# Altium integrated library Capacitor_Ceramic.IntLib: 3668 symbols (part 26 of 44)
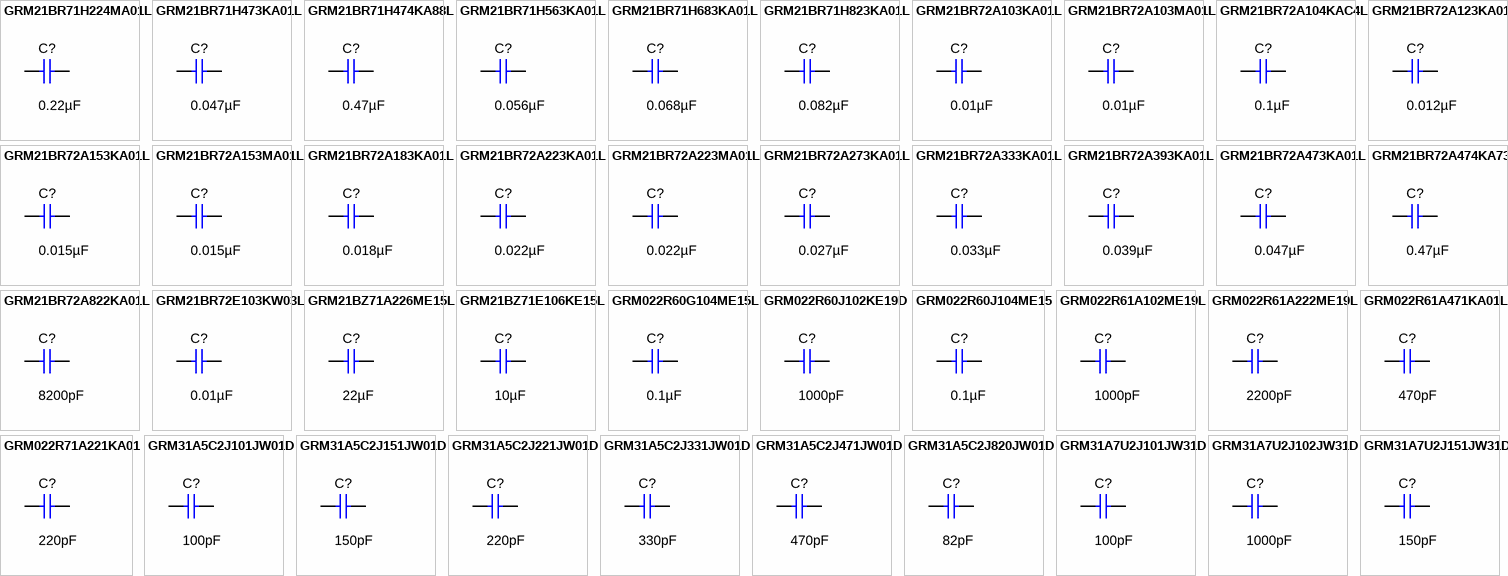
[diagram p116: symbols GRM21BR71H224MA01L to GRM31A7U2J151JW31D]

## GRM022R61A222ME19L
designator C?  ValueDisplayed: 2200pF  (hidden comment: GRM022R61A222ME19L)
CAP, CERM, 2200 pF, 10 V,+/- 20%, X5R, 01005; Manufacturer: MuRata; Polarized: N; CompType: Capacitor; Value: 2200pF; U/M: EA; Cap_F: 0.0000000022; Tolerance_%: 20; VDC_V: 10; Value2: 10V; TaMin_C: -55; TaMax_C: 85; Cap_Case: 01005; SizeArea_mm2: 0.08; SizeAreaWB_mm2: 1.68; SizeX_mm: 0.4; SizeY_mm: 0.2; AEC Category: Q200
signal-integrity model Cap
simulation model Cap
footprint 01005
pins: 1, 2

## GRM022R61A471KA01L
designator C?  ValueDisplayed: 470pF  (hidden comment: GRM022R61A471KA01L)
CAP, CERM, 470 pF, 10 V,+/- 10%, X5R, 01005; Manufacturer: MuRata; Polarized: N; CompType: Capacitor; Value: 470pF; U/M: EA; Cap_F: 0.00000000047; Tolerance_%: 10; Value2: 10V; TaMin_C: -55; TaMax_C: 85; Cap_Case: 01005; SizeArea_mm2: 0.08; SizeAreaWB_mm2: 1.68; SizeX_mm: 0.4; SizeY_mm: 0.2; AEC Category: Q200
signal-integrity model Cap
simulation model Cap
footprint 01005
pins: 1, 2

## GRM022R71A221KA01
designator C?  ValueDisplayed: 220pF  (hidden comment: GRM022R71A221KA01)
CAP, CERM, 220 pF, 10 V,+/- 10%, X7R, 01005; Manufacturer: MuRata; Polarized: N; CompType: Capacitor; Value: 220pF; U/M: EA; Cap_F: 0.00000000022; Tolerance_%: 10; Value2: 10V; TaMin_C: -55; TaMax_C: 125; Cap_Case: 01005; SizeArea_mm2: 0.08; SizeAreaWB_mm2: 1.68; SizeX_mm: 0.4; SizeY_mm: 0.2; AEC Category: Q200
signal-integrity model Cap
simulation model Cap
footprint 01005
pins: 1, 2

## GRM31A5C2J101JW01D
designator C?  ValueDisplayed: 100pF  (hidden comment: GRM31A5C2J101JW01D)
CAP, CERM, 100 pF, 630 V,+/- 5%, C0G/NP0, 1206; Manufacturer: MuRata; Polarized: N; CompType: Capacitor; Value: 100pF; U/M: EA; Cap_F: 0.0000000001; Tolerance_%: 5; VDC_V: 630; Value2: 630V; TaMin_C: -55; TaMax_C: 125; Cap_Case: 1206; SizeArea_mm2: 5.12; SizeAreaWB_mm2: 10.92; SizeX_mm: 3.2; SizeY_mm: 1.6; SizeZ_mm: 1.35; AEC Category: Q200; Green_Lifecycle: Not Set; Green_REACh: Incomplete
signal-integrity model Cap
simulation model Cap
footprint 1206
footprint 1206M
footprint 1206L
pins: 1, 2

## GRM31A5C2J151JW01D
designator C?  ValueDisplayed: 150pF  (hidden comment: GRM31A5C2J151JW01D)
CAP, CERM, 150 pF, 630 V,+/- 5%, C0G/NP0, 1206; Manufacturer: MuRata; Polarized: N; CompType: Capacitor; Value: 150pF; U/M: EA; Cap_F: 0.00000000015; Tolerance_%: 5; VDC_V: 630; Value2: 630V; TaMin_C: -55; TaMax_C: 125; Cap_Case: 1206; SizeArea_mm2: 5.12; SizeAreaWB_mm2: 10.92; SizeX_mm: 3.2; SizeY_mm: 1.6; SizeZ_mm: 1.35; AEC Category: Q200
signal-integrity model Cap
simulation model Cap
footprint 1206
footprint 1206M
footprint 1206L
pins: 1, 2

## GRM31A5C2J221JW01D
designator C?  ValueDisplayed: 220pF  (hidden comment: GRM31A5C2J221JW01D)
CAP, CERM, 220 pF, 630 V,+/- 5%, C0G/NP0, 1206; Manufacturer: MuRata; Polarized: N; CompType: Capacitor; Value: 220pF; U/M: EA; Cap_F: 0.00000000022; Tolerance_%: 5; VDC_V: 630; Value2: 630V; TaMin_C: -55; TaMax_C: 125; Cap_Case: 1206; SizeArea_mm2: 5.12; SizeAreaWB_mm2: 10.92; SizeX_mm: 3.2; SizeY_mm: 1.6; SizeZ_mm: 1.35; AEC Category: Q200
signal-integrity model Cap
simulation model Cap
footprint 1206
footprint 1206M
footprint 1206L
pins: 1, 2

## GRM31A5C2J331JW01D
designator C?  ValueDisplayed: 330pF  (hidden comment: GRM31A5C2J331JW01D)
CAP, CERM, 330 pF, 630 V,+/- 5%, C0G/NP0, 1206; Manufacturer: MuRata; Polarized: N; CompType: Capacitor; Value: 330pF; U/M: EA; Cap_F: 0.00000000033; Tolerance_%: 5; VDC_V: 630; Value2: 630V; TaMin_C: -55; TaMax_C: 125; Cap_Case: 1206; SizeArea_mm2: 5.12; SizeAreaWB_mm2: 10.92; SizeX_mm: 3.2; SizeY_mm: 1.6; SizeZ_mm: 1.35; AEC Category: Q200
signal-integrity model Cap
simulation model Cap
footprint 1206
footprint 1206M
footprint 1206L
pins: 1, 2

## GRM31A5C2J471JW01D
designator C?  ValueDisplayed: 470pF  (hidden comment: GRM31A5C2J471JW01D)
CAP, CERM, 470 pF, 630 V,+/- 5%, C0G/NP0, 1206; Manufacturer: MuRata; Polarized: N; CompType: Capacitor; Value: 470pF; U/M: EA; Cap_F: 0.00000000047; Tolerance_%: 5; VDC_V: 630; Value2: 630V; TaMin_C: -55; TaMax_C: 125; Cap_Case: 1206; SizeArea_mm2: 5.12; SizeAreaWB_mm2: 10.92; SizeX_mm: 3.2; SizeY_mm: 1.6; SizeZ_mm: 1.35; AEC Category: Q200; Green_Lifecycle: Not Set; Green_REACh: Incomplete
signal-integrity model Cap
simulation model Cap
footprint 1206
footprint 1206M
footprint 1206L
pins: 1, 2

## GRM31A5C2J820JW01D
designator C?  ValueDisplayed: 82pF  (hidden comment: GRM31A5C2J820JW01D)
CAP, CERM, 82 pF, 630 V,+/- 5%, C0G/NP0, 1206; Manufacturer: MuRata; Polarized: N; CompType: Capacitor; Value: 82pF; U/M: EA; Cap_F: 0.000000000082; Tolerance_%: 5; VDC_V: 630; Value2: 630V; TaMin_C: -55; TaMax_C: 125; Cap_Case: 1206; SizeArea_mm2: 5.12; SizeAreaWB_mm2: 10.92; SizeX_mm: 3.2; SizeY_mm: 1.6; SizeZ_mm: 1.35; AEC Category: Q200
signal-integrity model Cap
simulation model Cap
footprint 1206
footprint 1206M
footprint 1206L
pins: 1, 2

## GRM31A7U2J101JW31D
designator C?  ValueDisplayed: 100pF  (hidden comment: GRM31A7U2J101JW31D)
CAP, CERM, 100 pF, 630 V,+/- 5%, U2J, 1206; Manufacturer: MuRata; Polarized: N; CompType: Capacitor; Value: 100pF; U/M: EA; Cap_F: 0.0000000001; Tolerance_%: 5; VDC_V: 630; Value2: 630V; TaMin_C: -55; TaMax_C: 125; Cap_Case: 1206; SizeArea_mm2: 5.12; SizeAreaWB_mm2: 10.92; SizeX_mm: 3.2; SizeY_mm: 1.6; SizeZ_mm: 1.35; AEC Category: Q200
signal-integrity model Cap
simulation model Cap
footprint 1206
footprint 1206M
footprint 1206L
pins: 1, 2

## GRM31A7U2J102JW31D
designator C?  ValueDisplayed: 1000pF  (hidden comment: GRM31A7U2J102JW31D)
CAP, CERM, 1000 pF, 630 V,+/- 5%, U2J, 1206; Manufacturer: MuRata; Polarized: N; CompType: Capacitor; Value: 1000pF; U/M: EA; Cap_F: 0.000000001; Tolerance_%: 5; VDC_V: 630; Value2: 630V; TaMin_C: -55; TaMax_C: 125; Cap_Case: 1206; SizeArea_mm2: 5.12; SizeAreaWB_mm2: 10.92; SizeX_mm: 3.2; SizeY_mm: 1.6; SizeZ_mm: 1.35; AEC Category: Q200
signal-integrity model Cap
simulation model Cap
footprint 1206
footprint 1206M
footprint 1206L
pins: 1, 2

## GRM31A7U2J151JW31D
designator C?  ValueDisplayed: 150pF  (hidden comment: GRM31A7U2J151JW31D)
CAP, CERM, 150 pF, 630 V,+/- 5%, U2J, 1206; Manufacturer: MuRata; Polarized: N; CompType: Capacitor; Value: 150pF; U/M: EA; Cap_F: 0.00000000015; Tolerance_%: 5; VDC_V: 630; Value2: 630V; TaMin_C: -55; TaMax_C: 125; Cap_Case: 1206; SizeArea_mm2: 5.12; SizeAreaWB_mm2: 10.92; SizeX_mm: 3.2; SizeY_mm: 1.6; SizeZ_mm: 1.35; AEC Category: Q200
signal-integrity model Cap
simulation model Cap
footprint 1206
footprint 1206M
footprint 1206L
pins: 1, 2

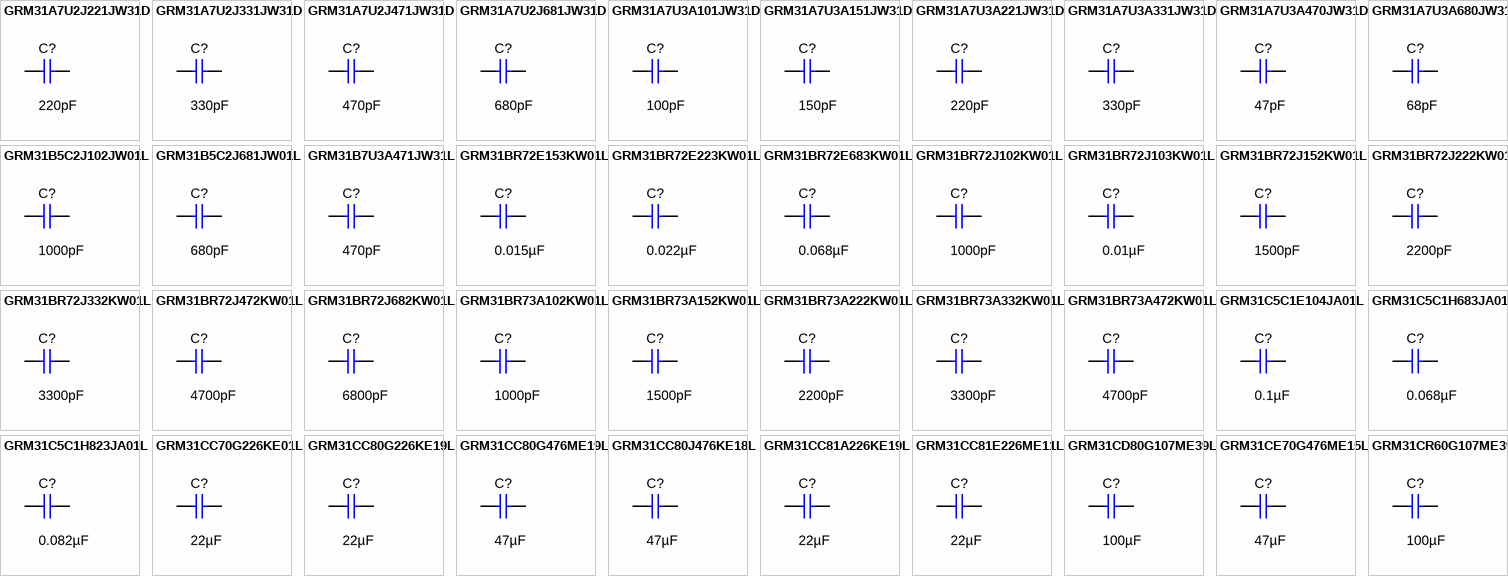
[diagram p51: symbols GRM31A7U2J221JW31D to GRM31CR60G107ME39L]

## GRM31A7U2J221JW31D
designator C?  ValueDisplayed: 220pF  (hidden comment: GRM31A7U2J221JW31D)
CAP, CERM, 220 pF, 630 V,+/- 5%, U2J, 1206; Manufacturer: MuRata; Polarized: N; CompType: Capacitor; Value: 220pF; U/M: EA; Cap_F: 0.00000000022; Tolerance_%: 5; VDC_V: 630; Value2: 630V; TaMin_C: -55; TaMax_C: 125; Cap_Case: 1206; SizeArea_mm2: 5.12; SizeAreaWB_mm2: 10.92; SizeX_mm: 3.2; SizeY_mm: 1.6; SizeZ_mm: 1.35; AEC Category: Q200
signal-integrity model Cap
simulation model Cap
footprint 1206
footprint 1206M
footprint 1206L
pins: 1, 2

## GRM31A7U2J331JW31D
designator C?  ValueDisplayed: 330pF  (hidden comment: GRM31A7U2J331JW31D)
CAP, CERM, 330 pF, 630 V,+/- 5%, U2J, 1206; Manufacturer: MuRata; Polarized: N; CompType: Capacitor; Value: 330pF; U/M: EA; Cap_F: 0.00000000033; Tolerance_%: 5; VDC_V: 630; Value2: 630V; TaMin_C: -55; TaMax_C: 125; Cap_Case: 1206; SizeArea_mm2: 5.12; SizeAreaWB_mm2: 10.92; SizeX_mm: 3.2; SizeY_mm: 1.6; SizeZ_mm: 1.35; AEC Category: Q200
signal-integrity model Cap
simulation model Cap
footprint 1206
footprint 1206M
footprint 1206L
pins: 1, 2

## GRM31A7U2J471JW31D
designator C?  ValueDisplayed: 470pF  (hidden comment: GRM31A7U2J471JW31D)
CAP, CERM, 470 pF, 630 V,+/- 5%, U2J, 1206; Manufacturer: MuRata; Polarized: N; CompType: Capacitor; Value: 470pF; U/M: EA; Cap_F: 0.00000000047; Tolerance_%: 5; VDC_V: 630; Value2: 630V; TaMin_C: -55; TaMax_C: 125; Cap_Case: 1206; SizeArea_mm2: 5.12; SizeAreaWB_mm2: 10.92; SizeX_mm: 3.2; SizeY_mm: 1.6; SizeZ_mm: 1.35; AEC Category: Q200; Green_Lifecycle: Not Set; Green_REACh: Incomplete
signal-integrity model Cap
simulation model Cap
footprint 1206
footprint 1206M
footprint 1206L
pins: 1, 2

## GRM31A7U2J681JW31D
designator C?  ValueDisplayed: 680pF  (hidden comment: GRM31A7U2J681JW31D)
CAP, CERM, 680 pF, 630 V,+/- 5%, U2J, 1206; Manufacturer: MuRata; Polarized: N; CompType: Capacitor; Value: 680pF; U/M: EA; Cap_F: 0.00000000068; Tolerance_%: 5; VDC_V: 630; Value2: 630V; TaMin_C: -55; TaMax_C: 125; Cap_Case: 1206; SizeArea_mm2: 5.12; SizeAreaWB_mm2: 10.92; SizeX_mm: 3.2; SizeY_mm: 1.6; SizeZ_mm: 1.35; AEC Category: Q200
signal-integrity model Cap
simulation model Cap
footprint 1206
footprint 1206M
footprint 1206L
pins: 1, 2

## GRM31A7U3A101JW31D
designator C?  ValueDisplayed: 100pF  (hidden comment: GRM31A7U3A101JW31D)
CAP, CERM, 100 pF, 1000 V,+/- 5%, U2J, 1206; Manufacturer: MuRata; Polarized: N; CompType: Capacitor; Value: 100pF; U/M: EA; Cap_F: 0.0000000001; Tolerance_%: 5; VDC_V: 1000; Value2: 1000V; TaMin_C: -55; TaMax_C: 125; Cap_Case: 1206; SizeArea_mm2: 5.12; SizeAreaWB_mm2: 10.92; SizeX_mm: 3.2; SizeY_mm: 1.6; SizeZ_mm: 1.35; AEC Category: Q200
signal-integrity model Cap
simulation model Cap
footprint 1206
footprint 1206M
footprint 1206L
pins: 1, 2

## GRM31A7U3A151JW31D
designator C?  ValueDisplayed: 150pF  (hidden comment: GRM31A7U3A151JW31D)
CAP, CERM, 150 pF, 1000 V,+/- 5%, U2J, 1206; Manufacturer: MuRata; Polarized: N; CompType: Capacitor; Value: 150pF; U/M: EA; Cap_F: 0.00000000015; Tolerance_%: 5; VDC_V: 1000; Value2: 1000V; TaMin_C: -55; TaMax_C: 125; Cap_Case: 1206; SizeArea_mm2: 5.12; SizeAreaWB_mm2: 10.92; SizeX_mm: 3.2; SizeY_mm: 1.6; SizeZ_mm: 1.35; AEC Category: Q200
signal-integrity model Cap
simulation model Cap
footprint 1206
footprint 1206M
footprint 1206L
pins: 1, 2

## GRM31A7U3A221JW31D
designator C?  ValueDisplayed: 220pF  (hidden comment: GRM31A7U3A221JW31D)
CAP, CERM, 220 pF, 1000 V,+/- 5%, U2J, 1206; Manufacturer: MuRata; Polarized: N; CompType: Capacitor; Value: 220pF; U/M: EA; Cap_F: 0.00000000022; Tolerance_%: 5; VDC_V: 1000; Value2: 1000V; TaMin_C: -55; TaMax_C: 125; Cap_Case: 1206; SizeArea_mm2: 5.12; SizeAreaWB_mm2: 10.92; SizeX_mm: 3.2; SizeY_mm: 1.6; SizeZ_mm: 1.35; AEC Category: Q200
signal-integrity model Cap
simulation model Cap
footprint 1206
footprint 1206M
footprint 1206L
pins: 1, 2

## GRM31A7U3A331JW31D
designator C?  ValueDisplayed: 330pF  (hidden comment: GRM31A7U3A331JW31D)
CAP, CERM, 330 pF, 1000 V,+/- 5%, U2J, 1206; Manufacturer: MuRata; Polarized: N; CompType: Capacitor; Value: 330pF; U/M: EA; Cap_F: 0.00000000033; Tolerance_%: 5; VDC_V: 1000; Value2: 1000V; TaMin_C: -55; TaMax_C: 125; Cap_Case: 1206; SizeArea_mm2: 5.12; SizeAreaWB_mm2: 10.92; SizeX_mm: 3.2; SizeY_mm: 1.6; SizeZ_mm: 1.35; AEC Category: Q200
signal-integrity model Cap
simulation model Cap
footprint 1206
footprint 1206M
footprint 1206L
pins: 1, 2

## GRM31A7U3A470JW31D
designator C?  ValueDisplayed: 47pF  (hidden comment: GRM31A7U3A470JW31D)
CAP, CERM, 47 pF, 1000 V,+/- 5%, U2J, 1206; Manufacturer: MuRata; Polarized: N; CompType: Capacitor; Value: 47pF; U/M: EA; Cap_F: 0.000000000047; Tolerance_%: 5; VDC_V: 1000; Value2: 1000V; TaMin_C: -55; TaMax_C: 125; Cap_Case: 1206; SizeArea_mm2: 5.12; SizeAreaWB_mm2: 10.92; SizeX_mm: 3.2; SizeY_mm: 1.6; SizeZ_mm: 1.35; AEC Category: Q200
signal-integrity model Cap
simulation model Cap
footprint 1206
footprint 1206M
footprint 1206L
pins: 1, 2

## GRM31A7U3A680JW31D
designator C?  ValueDisplayed: 68pF  (hidden comment: GRM31A7U3A680JW31D)
CAP, CERM, 68 pF, 1000 V,+/- 5%, U2J, 1206; Manufacturer: MuRata; Polarized: N; CompType: Capacitor; Value: 68pF; U/M: EA; Cap_F: 0.000000000068; Tolerance_%: 5; VDC_V: 1000; Value2: 1000V; TaMin_C: -55; TaMax_C: 125; Cap_Case: 1206; SizeArea_mm2: 5.12; SizeAreaWB_mm2: 10.92; SizeX_mm: 3.2; SizeY_mm: 1.6; SizeZ_mm: 1.35; AEC Category: Q200
signal-integrity model Cap
simulation model Cap
footprint 1206
footprint 1206M
footprint 1206L
pins: 1, 2

## GRM31B5C2J102JW01L
designator C?  ValueDisplayed: 1000pF  (hidden comment: GRM31B5C2J102JW01L)
CAP, CERM, 1000 pF, 630 V,+/- 5%, C0G/NP0, 1206; Manufacturer: MuRata; Polarized: N; CompType: Capacitor; Value: 1000pF; U/M: EA; Cap_F: 0.000000001; Tolerance_%: 5; VDC_V: 630; Value2: 630V; TaMin_C: -55; TaMax_C: 125; Cap_Case: 1206; SizeArea_mm2: 5.12; SizeAreaWB_mm2: 10.92; SizeX_mm: 3.2; SizeY_mm: 1.6; SizeZ_mm: 1.35; AEC Category: Q200; Green_Lifecycle: Not Set; Green_REACh: Incomplete
signal-integrity model Cap
simulation model Cap
footprint 1206
footprint 1206M
footprint 1206L
pins: 1, 2

## GRM31B5C2J681JW01L
designator C?  ValueDisplayed: 680pF  (hidden comment: GRM31B5C2J681JW01L)
CAP, CERM, 680 pF, 630 V,+/- 5%, C0G/NP0, 1206; Manufacturer: MuRata; Polarized: N; CompType: Capacitor; Value: 680pF; U/M: EA; Cap_F: 0.00000000068; Tolerance_%: 5; VDC_V: 630; Value2: 630V; TaMin_C: -55; TaMax_C: 125; Cap_Case: 1206; SizeArea_mm2: 5.12; SizeAreaWB_mm2: 10.92; SizeX_mm: 3.2; SizeY_mm: 1.6; SizeZ_mm: 1.35; AEC Category: Q200
signal-integrity model Cap
simulation model Cap
footprint 1206
footprint 1206M
footprint 1206L
pins: 1, 2

## GRM31B7U3A471JW31L
designator C?  ValueDisplayed: 470pF  (hidden comment: GRM31B7U3A471JW31L)
CAP, CERM, 470 pF, 1000 V,+/- 5%, U2J, 1206; Manufacturer: MuRata; Polarized: N; CompType: Capacitor; Value: 470pF; U/M: EA; Cap_F: 0.00000000047; Tolerance_%: 5; VDC_V: 1000; Value2: 1000V; TaMin_C: -55; TaMax_C: 125; Cap_Case: 1206; SizeArea_mm2: 5.12; SizeAreaWB_mm2: 10.92; SizeX_mm: 3.2; SizeY_mm: 1.6; SizeZ_mm: 1.35; AEC Category: Q200
signal-integrity model Cap
simulation model Cap
footprint 1206
footprint 1206M
footprint 1206L
pins: 1, 2

## GRM31BR72E153KW01L
designator C?  ValueDisplayed: 0.015µF  (hidden comment: GRM31BR72E153KW01L)
CAP, CERM, 0.015 µF, 250 V,+/- 10%, X7R, 1206; Manufacturer: MuRata; Polarized: N; CompType: Capacitor; Value: 0.015uF; U/M: EA; Cap_F: 0.000000015; Tolerance_%: 10; VDC_V: 250; Value2: 250V; TaMin_C: -55; TaMax_C: 125; Cap_Case: 1206; SizeArea_mm2: 5.12; SizeAreaWB_mm2: 10.92; SizeX_mm: 3.2; SizeY_mm: 1.6; SizeZ_mm: 1.35; AEC Category: Q200; Green_Lifecycle: Not Set; Green_REACh: Incomplete
signal-integrity model Cap
simulation model Cap
footprint 1206
footprint 1206M
footprint 1206L
pins: 1, 2

## GRM31BR72E223KW01L
designator C?  ValueDisplayed: 0.022µF  (hidden comment: GRM31BR72E223KW01L)
CAP, CERM, 0.022 µF, 250 V,+/- 10%, X7R, 1206; Manufacturer: MuRata; Polarized: N; CompType: Capacitor; Value: 0.022uF; U/M: EA; Cap_F: 0.000000022; Tolerance_%: 10; VDC_V: 250; Value2: 250V; TaMin_C: -55; TaMax_C: 125; Cap_Case: 1206; SizeArea_mm2: 5.12; SizeAreaWB_mm2: 10.92; SizeX_mm: 3.2; SizeY_mm: 1.6; SizeZ_mm: 1.35; AEC Category: Q200
signal-integrity model Cap
simulation model Cap
footprint 1206
footprint 1206M
footprint 1206L
pins: 1, 2

## GRM31BR72E683KW01L
designator C?  ValueDisplayed: 0.068µF  (hidden comment: GRM31BR72E683KW01L)
CAP, CERM, 0.068 µF, 250 V,+/- 10%, X7R, 1206; Manufacturer: MuRata; Polarized: N; CompType: Capacitor; Value: 0.068uF; U/M: EA; Cap_F: 0.000000068; Tolerance_%: 10; VDC_V: 250; Value2: 250V; TaMin_C: -55; TaMax_C: 125; Cap_Case: 1206; SizeArea_mm2: 5.12; SizeAreaWB_mm2: 10.92; SizeX_mm: 3.2; SizeY_mm: 1.6; SizeZ_mm: 1.35; AEC Category: Q200
signal-integrity model Cap
simulation model Cap
footprint 1206
footprint 1206M
footprint 1206L
pins: 1, 2

## GRM31BR72J102KW01L
designator C?  ValueDisplayed: 1000pF  (hidden comment: GRM31BR72J102KW01L)
CAP, CERM, 1000 pF, 630 V,+/- 10%, X7R, 1206; Manufacturer: MuRata; Polarized: N; CompType: Capacitor; Value: 1000pF; U/M: EA; Cap_F: 0.000000001; Tolerance_%: 10; VDC_V: 630; Value2: 630V; TaMin_C: -55; TaMax_C: 125; Cap_Case: 1206; SizeArea_mm2: 5.12; SizeAreaWB_mm2: 10.92; SizeX_mm: 3.2; SizeY_mm: 1.6; SizeZ_mm: 1.35; AEC Category: Q200; Green_Lifecycle: Not Set; Green_REACh: Incomplete
signal-integrity model Cap
simulation model Cap
footprint 1206
footprint 1206M
footprint 1206L
pins: 1, 2

## GRM31BR72J103KW01L
designator C?  ValueDisplayed: 0.01µF  (hidden comment: GRM31BR72J103KW01L)
CAP, CERM, 0.01 µF, 630 V,+/- 10%, X7R, 1206; Manufacturer: MuRata; Polarized: N; CompType: Capacitor; Value: 0.01uF; U/M: EA; Cap_F: 0.00000001; Tolerance_%: 10; VDC_V: 630; Value2: 630V; TaMin_C: -55; TaMax_C: 125; Cap_Case: 1206; SizeArea_mm2: 5.12; SizeAreaWB_mm2: 10.92; SizeX_mm: 3.2; SizeY_mm: 1.6; SizeZ_mm: 1.35; AEC Category: Q200; Green_Lifecycle: Active; Green_REACh: Passed
signal-integrity model Cap
simulation model Cap
footprint 1206
footprint 1206M
footprint 1206L
pins: 1, 2

## GRM31BR72J152KW01L
designator C?  ValueDisplayed: 1500pF  (hidden comment: GRM31BR72J152KW01L)
CAP, CERM, 1500 pF, 630 V,+/- 10%, X7R, 1206; Manufacturer: MuRata; Polarized: N; CompType: Capacitor; Value: 1500pF; U/M: EA; Cap_F: 0.0000000015; Tolerance_%: 10; VDC_V: 630; Value2: 630V; TaMin_C: -55; TaMax_C: 125; Cap_Case: 1206; SizeArea_mm2: 5.12; SizeAreaWB_mm2: 10.92; SizeX_mm: 3.2; SizeY_mm: 1.6; SizeZ_mm: 1.35; AEC Category: Q200
signal-integrity model Cap
simulation model Cap
footprint 1206
footprint 1206M
footprint 1206L
pins: 1, 2

## GRM31BR72J222KW01L
designator C?  ValueDisplayed: 2200pF  (hidden comment: GRM31BR72J222KW01L)
CAP, CERM, 2200 pF, 630 V,+/- 10%, X7R, 1206; Manufacturer: MuRata; Polarized: N; CompType: Capacitor; Value: 2200pF; U/M: EA; Cap_F: 0.0000000022; Tolerance_%: 10; VDC_V: 630; Value2: 630V; TaMin_C: -55; TaMax_C: 125; Cap_Case: 1206; SizeArea_mm2: 5.12; SizeAreaWB_mm2: 10.92; SizeX_mm: 3.2; SizeY_mm: 1.6; SizeZ_mm: 1.35; AEC Category: Q200; Green_Lifecycle: Not Set; Green_REACh: Incomplete
signal-integrity model Cap
simulation model Cap
footprint 1206
footprint 1206M
footprint 1206L
pins: 1, 2

## GRM31BR72J332KW01L
designator C?  ValueDisplayed: 3300pF  (hidden comment: GRM31BR72J332KW01L)
CAP, CERM, 3300 pF, 630 V,+/- 10%, X7R, 1206; Manufacturer: MuRata; Polarized: N; CompType: Capacitor; Value: 3300pF; U/M: EA; Cap_F: 0.0000000033; Tolerance_%: 10; VDC_V: 630; Value2: 630V; TaMin_C: -55; TaMax_C: 125; Cap_Case: 1206; SizeArea_mm2: 5.12; SizeAreaWB_mm2: 10.92; SizeX_mm: 3.2; SizeY_mm: 1.6; SizeZ_mm: 1.35; AEC Category: Q200
signal-integrity model Cap
simulation model Cap
footprint 1206
footprint 1206M
footprint 1206L
pins: 1, 2

## GRM31BR72J472KW01L
designator C?  ValueDisplayed: 4700pF  (hidden comment: GRM31BR72J472KW01L)
CAP, CERM, 4700 pF, 630 V,+/- 10%, X7R, 1206; Manufacturer: MuRata; Polarized: N; CompType: Capacitor; Value: 4700pF; U/M: EA; Cap_F: 0.0000000047; Tolerance_%: 10; VDC_V: 630; Value2: 630V; TaMin_C: -55; TaMax_C: 125; Cap_Case: 1206; SizeArea_mm2: 5.12; SizeAreaWB_mm2: 10.92; SizeX_mm: 3.2; SizeY_mm: 1.6; SizeZ_mm: 1.35; AEC Category: Q200
signal-integrity model Cap
simulation model Cap
footprint 1206
footprint 1206M
footprint 1206L
pins: 1, 2

## GRM31BR72J682KW01L
designator C?  ValueDisplayed: 6800pF  (hidden comment: GRM31BR72J682KW01L)
CAP, CERM, 6800 pF, 630 V,+/- 10%, X7R, 1206; Manufacturer: MuRata; Polarized: N; CompType: Capacitor; Value: 6800pF; U/M: EA; Cap_F: 0.0000000068; Tolerance_%: 10; VDC_V: 630; Value2: 630V; TaMin_C: -55; TaMax_C: 125; Cap_Case: 1206; SizeArea_mm2: 5.12; SizeAreaWB_mm2: 10.92; SizeX_mm: 3.2; SizeY_mm: 1.6; SizeZ_mm: 1.35; AEC Category: Q200
signal-integrity model Cap
simulation model Cap
footprint 1206
footprint 1206M
footprint 1206L
pins: 1, 2

## GRM31BR73A102KW01L
designator C?  ValueDisplayed: 1000pF  (hidden comment: GRM31BR73A102KW01L)
CAP, CERM, 1000 pF, 1000 V,+/- 10%, X7R, 1206; Manufacturer: MuRata; Polarized: N; CompType: Capacitor; Value: 1000pF; U/M: EA; Cap_F: 0.000000001; Tolerance_%: 10; VDC_V: 1000; Value2: 1000V; TaMin_C: -55; TaMax_C: 125; Cap_Case: 1206; SizeArea_mm2: 5.12; SizeAreaWB_mm2: 10.92; SizeX_mm: 3.2; SizeY_mm: 1.6; SizeZ_mm: 1.35; AEC Category: Q200; Green_Lifecycle: Not Set; Green_REACh: Incomplete
signal-integrity model Cap
simulation model Cap
footprint 1206
footprint 1206M
footprint 1206L
pins: 1, 2

## GRM31BR73A152KW01L
designator C?  ValueDisplayed: 1500pF  (hidden comment: GRM31BR73A152KW01L)
CAP, CERM, 1500 pF, 1000 V,+/- 10%, X7R, 1206; Manufacturer: MuRata; Polarized: N; CompType: Capacitor; Value: 1500pF; U/M: EA; Cap_F: 0.0000000015; Tolerance_%: 10; VDC_V: 1000; Value2: 1000V; TaMin_C: -55; TaMax_C: 125; Cap_Case: 1206; SizeArea_mm2: 5.12; SizeAreaWB_mm2: 10.92; SizeX_mm: 3.2; SizeY_mm: 1.6; SizeZ_mm: 1.35; AEC Category: Q200
signal-integrity model Cap
simulation model Cap
footprint 1206
footprint 1206M
footprint 1206L
pins: 1, 2

## GRM31BR73A222KW01L
designator C?  ValueDisplayed: 2200pF  (hidden comment: GRM31BR73A222KW01L)
CAP, CERM, 2200 pF, 1000 V,+/- 10%, X7R, 1206; Manufacturer: MuRata; Polarized: N; CompType: Capacitor; Value: 2200pF; U/M: EA; Cap_F: 0.0000000022; Tolerance_%: 10; VDC_V: 1000; Value2: 1000V; TaMin_C: -55; TaMax_C: 125; Cap_Case: 1206; SizeArea_mm2: 5.12; SizeAreaWB_mm2: 10.92; SizeX_mm: 3.2; SizeY_mm: 1.6; SizeZ_mm: 1.35; AEC Category: Q200
signal-integrity model Cap
simulation model Cap
footprint 1206
footprint 1206M
footprint 1206L
pins: 1, 2

## GRM31BR73A332KW01L
designator C?  ValueDisplayed: 3300pF  (hidden comment: GRM31BR73A332KW01L)
CAP, CERM, 3300 pF, 1000 V,+/- 10%, X7R, 1206; Manufacturer: MuRata; Polarized: N; CompType: Capacitor; Value: 3300pF; U/M: EA; Cap_F: 0.0000000033; Tolerance_%: 10; VDC_V: 1000; Value2: 1000V; TaMin_C: -55; TaMax_C: 125; Cap_Case: 1206; SizeArea_mm2: 5.12; SizeAreaWB_mm2: 10.92; SizeX_mm: 3.2; SizeY_mm: 1.6; SizeZ_mm: 1.35; AEC Category: Q200
signal-integrity model Cap
simulation model Cap
footprint 1206
footprint 1206M
footprint 1206L
pins: 1, 2

## GRM31BR73A472KW01L
designator C?  ValueDisplayed: 4700pF  (hidden comment: GRM31BR73A472KW01L)
CAP, CERM, 4700 pF, 1000 V,+/- 10%, X7R, 1206; Manufacturer: MuRata; Polarized: N; CompType: Capacitor; Value: 4700pF; U/M: EA; Cap_F: 0.0000000047; Tolerance_%: 10; VDC_V: 1000; Value2: 1000V; TaMin_C: -55; TaMax_C: 125; Cap_Case: 1206; SizeArea_mm2: 5.12; SizeAreaWB_mm2: 10.92; SizeX_mm: 3.2; SizeY_mm: 1.6; SizeZ_mm: 1.35; AEC Category: Q200
signal-integrity model Cap
simulation model Cap
footprint 1206
footprint 1206M
footprint 1206L
pins: 1, 2

## GRM31C5C1E104JA01L
designator C?  ValueDisplayed: 0.1µF  (hidden comment: GRM31C5C1E104JA01L)
CAP, CERM, 0.1 µF, 25 V,+/- 5%, C0G/NP0, 1206; Manufacturer: MuRata; Polarized: N; CompType: Capacitor; Value: 0.1uF; U/M: EA; Cap_F: 0.0000001; Tolerance_%: 5; VDC_V: 25; Value2: 25V; TaMin_C: -55; TaMax_C: 125; Cap_Case: 1206; SizeArea_mm2: 5.12; SizeAreaWB_mm2: 10.92; SizeX_mm: 3.2; SizeY_mm: 1.6; SizeZ_mm: 1.8; AEC Category: Q200
signal-integrity model Cap
simulation model Cap
footprint 1206_180
footprint 1206_180M
footprint 1206_180L
pins: 1, 2

## GRM31C5C1H683JA01L
designator C?  ValueDisplayed: 0.068µF  (hidden comment: GRM31C5C1H683JA01L)
CAP, CERM, 0.068 µF, 50 V,+/- 5%, C0G/NP0, 1206; Manufacturer: MuRata; Polarized: N; CompType: Capacitor; Value: 0.068uF; U/M: EA; Cap_F: 0.000000068; Tolerance_%: 5; ESR_ohm: 0.01; Value1: 0.01 ohm; VDC_V: 50; Value2: 50V; IRMS_A: 0.9; TaMin_C: -55; TaMax_C: 125; Cap_Case: 1206; SizeArea_mm2: 5.12; SizeAreaWB_mm2: 10.92; SizeX_mm: 3.2; SizeY_mm: 1.6; SizeZ_mm: 1.8; AEC Category: Q200; Green_Lifecycle: Active; Green_REACh: Passed
signal-integrity model Cap
simulation model Cap
footprint 1206_180
footprint 1206_180M
footprint 1206_180L
pins: 1, 2

## GRM31C5C1H823JA01L
designator C?  ValueDisplayed: 0.082µF  (hidden comment: GRM31C5C1H823JA01L)
CAP, CERM, 0.082 µF, 50 V,+/- 5%, C0G/NP0, 1206; Manufacturer: MuRata; Polarized: N; CompType: Capacitor; Value: 0.082uF; U/M: EA; Cap_F: 0.000000082; Tolerance_%: 5; ESR_ohm: 0.01; Value1: 0.01 ohm; VDC_V: 50; Value2: 50V; IRMS_A: 0.9; TaMin_C: -55; TaMax_C: 125; Cap_Case: 1206; SizeArea_mm2: 5.12; SizeAreaWB_mm2: 10.92; SizeX_mm: 3.2; SizeY_mm: 1.6; SizeZ_mm: 1.8; AEC Category: Q200; Green_Lifecycle: Active; Green_REACh: Passed
signal-integrity model Cap
simulation model Cap
footprint 1206_180
footprint 1206_180M
footprint 1206_180L
pins: 1, 2

## GRM31CC70G226KE01L
designator C?  ValueDisplayed: 22µF  (hidden comment: GRM31CC70G226KE01L)
CAP, CERM, 22 µF, 4 V,+/- 10%, X7S, 1206; Manufacturer: MuRata; Polarized: N; CompType: Capacitor; Value: 22uF; U/M: EA; Cap_F: 0.000022; Tolerance_%: 10; VDC_V: 4; Value2: 4V; TaMin_C: -55; TaMax_C: 125; Cap_Case: 1206; SizeArea_mm2: 5.12; SizeAreaWB_mm2: 10.92; SizeX_mm: 3.2; SizeY_mm: 1.6; SizeZ_mm: 1.8; AEC Category: Q200
signal-integrity model Cap
simulation model Cap
footprint 1206_180
footprint 1206_180M
footprint 1206_180L
pins: 1, 2

## GRM31CC80G226KE19L
designator C?  ValueDisplayed: 22µF  (hidden comment: GRM31CC80G226KE19L)
CAP, CERM, 22 µF, 4 V,+/- 10%, X6S, 1206; Manufacturer: MuRata; Polarized: N; CompType: Capacitor; Value: 22uF; U/M: EA; Cap_F: 0.000022; Tolerance_%: 10; VDC_V: 4; Value2: 4V; TaMin_C: -55; TaMax_C: 105; Cap_Case: 1206; SizeArea_mm2: 5.12; SizeAreaWB_mm2: 10.92; SizeX_mm: 3.2; SizeY_mm: 1.6; SizeZ_mm: 1.8; AEC Category: Q200
signal-integrity model Cap
simulation model Cap
footprint 1206_180
footprint 1206_180M
footprint 1206_180L
pins: 1, 2

## GRM31CC80G476ME19L
designator C?  ValueDisplayed: 47µF  (hidden comment: GRM31CC80G476ME19L)
CAP, CERM, 47 µF, 4 V,+/- 20%, X6S, 1206; Manufacturer: MuRata; Polarized: N; CompType: Capacitor; Value: 47uF; U/M: EA; Cap_F: 0.000047; Tolerance_%: 20; VDC_V: 4; Value2: 4V; TaMin_C: -55; TaMax_C: 105; Cap_Case: 1206; SizeArea_mm2: 5.12; SizeAreaWB_mm2: 10.92; SizeX_mm: 3.2; SizeY_mm: 1.6; SizeZ_mm: 1.8; AEC Category: Q200
signal-integrity model Cap
simulation model Cap
footprint 1206_180
footprint 1206_180M
footprint 1206_180L
pins: 1, 2

## GRM31CC80J476KE18L
designator C?  ValueDisplayed: 47µF  (hidden comment: GRM31CC80J476KE18L)
CAP, CERM, 47 µF, 6.3 V,+/- 10%, X6S, 1206; Manufacturer: MuRata; Polarized: N; CompType: Capacitor; Value: 47uF; U/M: EA; Cap_F: 0.000047; Tolerance_%: 10; VDC_V: 6.3; Value2: 6.3V; TaMin_C: -55; TaMax_C: 105; Cap_Case: 1206; SizeArea_mm2: 5.12; SizeAreaWB_mm2: 10.92; SizeX_mm: 3.2; SizeY_mm: 1.6; SizeZ_mm: 1.8; AEC Category: Q200
signal-integrity model Cap
simulation model Cap
footprint 1206_180
footprint 1206_180M
footprint 1206_180L
pins: 1, 2

## GRM31CC81A226KE19L
designator C?  ValueDisplayed: 22µF  (hidden comment: GRM31CC81A226KE19L)
CAP, CERM, 22 µF, 10 V,+/- 10%, X6S, 1206; Manufacturer: MuRata; Polarized: N; CompType: Capacitor; Value: 22uF; U/M: EA; Cap_F: 0.000022; Tolerance_%: 10; Value2: 10V; TaMin_C: -55; TaMax_C: 105; Cap_Case: 1206; SizeArea_mm2: 5.12; SizeAreaWB_mm2: 10.92; SizeX_mm: 3.2; SizeY_mm: 1.6; SizeZ_mm: 1.8; AEC Category: Q200
signal-integrity model Cap
simulation model Cap
footprint 1206_180
footprint 1206_180M
footprint 1206_180L
pins: 1, 2

## GRM31CC81E226ME11L
designator C?  ValueDisplayed: 22µF  (hidden comment: GRM31CC81E226ME11L)
CAP, CERM, 22 µF, 25 V,+/- 20%, X6S, 1206; Manufacturer: MuRata; Polarized: N; CompType: Capacitor; Value: 22uF; U/M: EA; Cap_F: 0.000022; Tolerance_%: 20; VDC_V: 25; Value2: 25V; TaMin_C: -55; TaMax_C: 105; Cap_Case: 1206; SizeArea_mm2: 5.12; SizeAreaWB_mm2: 10.92; SizeX_mm: 3.2; SizeY_mm: 1.6; SizeZ_mm: 1.9; AEC Category: Q200
signal-integrity model Cap
simulation model Cap
footprint 1206_190
footprint 1206_190M
footprint 1206_190L
pins: 1, 2

## GRM31CD80G107ME39L
designator C?  ValueDisplayed: 100µF  (hidden comment: GRM31CD80G107ME39L)
CAP, CERM, 100 µF, 4 V,+/- 20%, X6T, 1206; Manufacturer: MuRata; Polarized: N; CompType: Capacitor; Value: 100uF; U/M: EA; Cap_F: 0.0001; Tolerance_%: 20; VDC_V: 4; Value2: 4V; TaMin_C: -55; TaMax_C: 105; Cap_Case: 1206; SizeArea_mm2: 5.12; SizeAreaWB_mm2: 10.92; SizeX_mm: 3.2; SizeY_mm: 1.6; SizeZ_mm: 1.8; AEC Category: Q200
signal-integrity model Cap
simulation model Cap
footprint 1206_180
footprint 1206_180M
footprint 1206_180L
pins: 1, 2

## GRM31CE70G476ME15L
designator C?  ValueDisplayed: 47µF  (hidden comment: GRM31CE70G476ME15L)
CAP, CERM, 47 µF, 4 V,+/- 20%, X7U, 1206; Manufacturer: MuRata; Polarized: N; CompType: Capacitor; Value: 47uF; U/M: EA; Cap_F: 0.000047; Tolerance_%: 20; VDC_V: 4; Value2: 4V; TaMin_C: -55; TaMax_C: 125; Cap_Case: 1206; SizeArea_mm2: 5.12; SizeAreaWB_mm2: 10.92; SizeX_mm: 3.2; SizeY_mm: 1.6; SizeZ_mm: 1.8; AEC Category: Q200
signal-integrity model Cap
simulation model Cap
footprint 1206_180
footprint 1206_180M
footprint 1206_180L
pins: 1, 2

## GRM31CR60G107ME39L
designator C?  ValueDisplayed: 100µF  (hidden comment: GRM31CR60G107ME39L)
CAP, CERM, 100 µF, 4 V,+/- 20%, X5R, 1206; Manufacturer: MuRata; Polarized: N; CompType: Capacitor; Value: 100uF; U/M: EA; Cap_F: 0.0001; Tolerance_%: 20; VDC_V: 4; Value2: 4V; TaMin_C: -55; TaMax_C: 85; Cap_Case: 1206; SizeArea_mm2: 5.12; SizeAreaWB_mm2: 10.92; SizeX_mm: 3.2; SizeY_mm: 1.6; SizeZ_mm: 1.8; AEC Category: Q200; Green_Lifecycle: Active; Green_REACh: Passed
signal-integrity model Cap
simulation model Cap
footprint 1206_180
footprint 1206_180M
footprint 1206_180L
pins: 1, 2

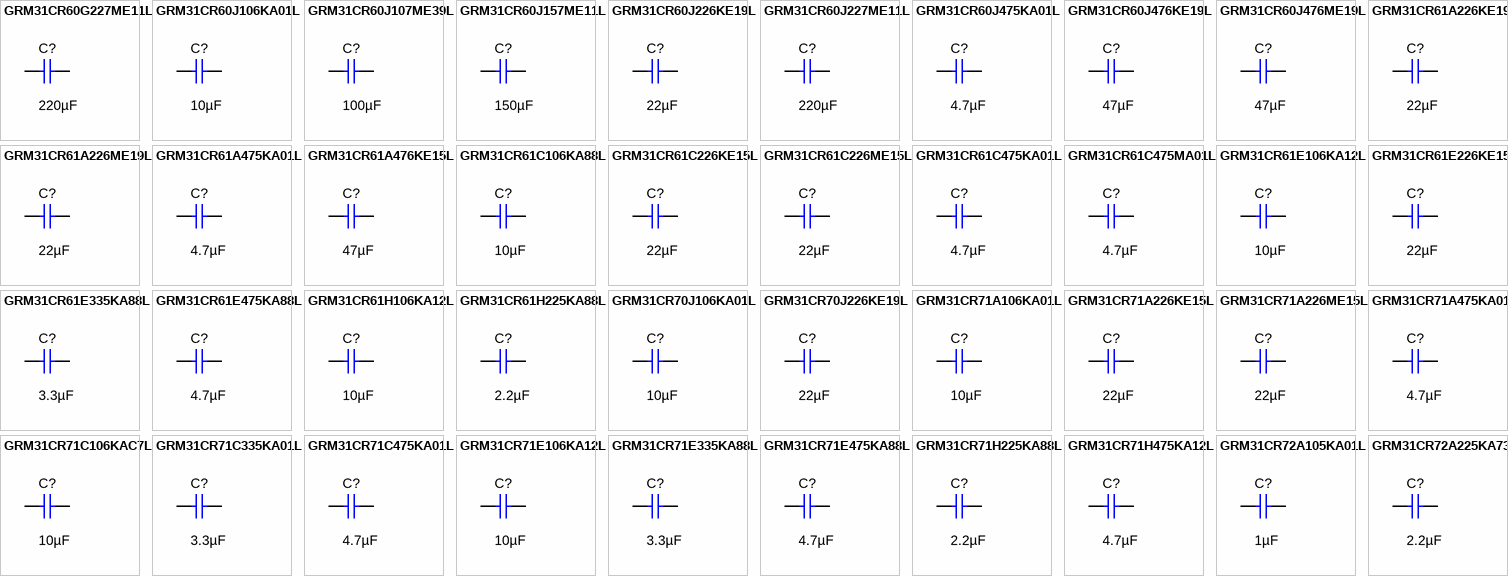
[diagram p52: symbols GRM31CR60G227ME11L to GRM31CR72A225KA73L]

## GRM31CR60G227ME11L
designator C?  ValueDisplayed: 220µF  (hidden comment: GRM31CR60G227ME11L)
CAP, CERM, 220 µF, 4 V,+/- 20%, X5R, 1206; Manufacturer: MuRata; Polarized: N; CompType: Capacitor; Value: 220uF; U/M: EA; Cap_F: 0.00022; Tolerance_%: 20; VDC_V: 4; Value2: 4V; TaMin_C: -55; TaMax_C: 85; Cap_Case: 1206; SizeArea_mm2: 5.12; SizeAreaWB_mm2: 10.92; SizeX_mm: 3.2; SizeY_mm: 1.6; SizeZ_mm: 1.9; AEC Category: Q200; Green_Lifecycle: Active; Green_REACh: Passed
signal-integrity model Cap
simulation model Cap
footprint 1206_190
footprint 1206_190M
footprint 1206_190L
pins: 1, 2

## GRM31CR60J106KA01L
designator C?  ValueDisplayed: 10µF  (hidden comment: GRM31CR60J106KA01L)
CAP, CERM, 10 µF, 6.3 V,+/- 10%, X5R, 1206; Manufacturer: MuRata; Polarized: N; CompType: Capacitor; Value: 10uF; U/M: EA; Cap_F: 0.00001; Tolerance_%: 10; VDC_V: 6.3; Value2: 6.3V; TaMin_C: -55; TaMax_C: 85; Cap_Case: 1206; SizeArea_mm2: 5.12; SizeAreaWB_mm2: 10.92; SizeX_mm: 3.2; SizeY_mm: 1.6; SizeZ_mm: 1.8; AEC Category: Q200
signal-integrity model Cap
simulation model Cap
footprint 1206_180
footprint 1206_180M
footprint 1206_180L
pins: 1, 2

## GRM31CR60J107ME39L
designator C?  ValueDisplayed: 100µF  (hidden comment: GRM31CR60J107ME39L)
CAP, CERM, 100 µF, 6.3 V,+/- 20%, X5R, 1206; Manufacturer: MuRata; Polarized: N; CompType: Capacitor; Value: 100uF; U/M: EA; Cap_F: 0.0001; Tolerance_%: 20; ESR_ohm: 0.003; Value1: 0.003 ohm; VDC_V: 6.3; Value2: 6.3V; TaMin_C: -55; TaMax_C: 85; Cap_Case: 1206; SizeArea_mm2: 5.12; SizeAreaWB_mm2: 10.92; SizeX_mm: 3.2; SizeY_mm: 1.6; SizeZ_mm: 1.8; AEC Category: Q200; Green_Lifecycle: Active; Green_REACh: Passed
signal-integrity model Cap
simulation model Cap
footprint 1206_180
footprint 1206_180M
footprint 1206_180L
pins: 1, 2

## GRM31CR60J157ME11L
designator C?  ValueDisplayed: 150µF  (hidden comment: GRM31CR60J157ME11L)
CAP, CERM, 150 µF, 6.3 V,+/- 20%, X5R, 1206; Manufacturer: MuRata; Polarized: N; CompType: Capacitor; Value: 150uF; U/M: EA; Cap_F: 0.00015; Tolerance_%: 20; VDC_V: 6.3; Value2: 6.3V; TaMin_C: -55; TaMax_C: 85; Cap_Case: 1206; SizeArea_mm2: 5.12; SizeAreaWB_mm2: 10.92; SizeX_mm: 3.2; SizeY_mm: 1.6; SizeZ_mm: 1.9; AEC Category: Q200
signal-integrity model Cap
simulation model Cap
footprint 1206_190
footprint 1206_190M
footprint 1206_190L
pins: 1, 2

## GRM31CR60J226KE19L
designator C?  ValueDisplayed: 22µF  (hidden comment: GRM31CR60J226KE19L)
CAP, CERM, 22 µF, 6.3 V,+/- 10%, X5R, 1206; Manufacturer: MuRata; Polarized: N; CompType: Capacitor; Value: 22uF; U/M: EA; Cap_F: 0.000022; Tolerance_%: 10; ESR_ohm: 0.003; Value1: 0.003 ohm; VDC_V: 6.3; Value2: 6.3V; TaMin_C: -55; TaMax_C: 85; Cap_Case: 1206; SizeArea_mm2: 5.12; SizeAreaWB_mm2: 10.92; SizeX_mm: 3.2; SizeY_mm: 1.6; SizeZ_mm: 1.8; AEC Category: Q200; Green_Lifecycle: Active; Green_REACh: Passed
signal-integrity model Cap
simulation model Cap
footprint 1206_180
footprint 1206_180M
footprint 1206_180L
pins: 1, 2

## GRM31CR60J227ME11L
designator C?  ValueDisplayed: 220µF  (hidden comment: GRM31CR60J227ME11L)
CAP, CERM, 220 µF, 6.3 V,+/- 20%, X5R, 1206; Manufacturer: MuRata; Polarized: N; CompType: Capacitor; Value: 220uF; U/M: EA; Cap_F: 0.00022; Tolerance_%: 20; VDC_V: 6.3; Value2: 6.3V; TaMin_C: -55; TaMax_C: 85; Cap_Case: 1206; SizeArea_mm2: 5.12; SizeAreaWB_mm2: 10.92; SizeX_mm: 3.2; SizeY_mm: 1.6; SizeZ_mm: 1.9; AEC Category: Q200
signal-integrity model Cap
simulation model Cap
footprint 1206_190
footprint 1206_190M
footprint 1206_190L
pins: 1, 2

## GRM31CR60J475KA01L
designator C?  ValueDisplayed: 4.7µF  (hidden comment: GRM31CR60J475KA01L)
CAP, CERM, 4.7 µF, 6.3 V,+/- 10%, X5R, 1206; Manufacturer: MuRata; Polarized: N; CompType: Capacitor; Value: 4.7uF; U/M: EA; Cap_F: 0.0000047; Tolerance_%: 10; VDC_V: 6.3; Value2: 6.3V; TaMin_C: -55; TaMax_C: 85; Cap_Case: 1206; SizeArea_mm2: 5.12; SizeAreaWB_mm2: 10.92; SizeX_mm: 3.2; SizeY_mm: 1.6; SizeZ_mm: 1.8; AEC Category: Q200
signal-integrity model Cap
simulation model Cap
footprint 1206_180
footprint 1206_180M
footprint 1206_180L
pins: 1, 2

## GRM31CR60J476KE19L
designator C?  ValueDisplayed: 47µF  (hidden comment: GRM31CR60J476KE19L)
CAP, CERM, 47 µF, 6.3 V,+/- 10%, X5R, 1206; Manufacturer: MuRata; Polarized: N; CompType: Capacitor; Value: 47uF; U/M: EA; Cap_F: 0.000047; Tolerance_%: 10; VDC_V: 6.3; Value2: 6.3V; TaMin_C: -55; TaMax_C: 85; Cap_Case: 1206; SizeArea_mm2: 5.12; SizeAreaWB_mm2: 10.92; SizeX_mm: 3.2; SizeY_mm: 1.6; SizeZ_mm: 1.8; AEC Category: Q200; Green_Lifecycle: Active; Green_REACh: Passed
signal-integrity model Cap
simulation model Cap
footprint 1206_180
footprint 1206_180M
footprint 1206_180L
pins: 1, 2

## GRM31CR60J476ME19L
designator C?  ValueDisplayed: 47µF  (hidden comment: GRM31CR60J476ME19L)
CAP, CERM, 47 µF, 6.3 V,+/- 20%, X5R, 1206; Manufacturer: MuRata; Polarized: N; CompType: Capacitor; Value: 47uF; U/M: EA; Cap_F: 0.000047; Tolerance_%: 20; ESR_ohm: 0.003; Value1: 0.003 ohm; VDC_V: 6.3; Value2: 6.3V; TaMin_C: -55; TaMax_C: 85; Cap_Case: 1206; SizeArea_mm2: 5.12; SizeAreaWB_mm2: 10.92; SizeX_mm: 3.2; SizeY_mm: 1.6; SizeZ_mm: 1.8; AEC Category: Q200; Green_Lifecycle: Active; Green_REACh: Passed
signal-integrity model Cap
simulation model Cap
footprint 1206_180
footprint 1206_180M
footprint 1206_180L
pins: 1, 2

## GRM31CR61A226KE19L
designator C?  ValueDisplayed: 22µF  (hidden comment: GRM31CR61A226KE19L)
CAP, CERM, 22 µF, 10 V,+/- 10%, X5R, 1206; Manufacturer: MuRata; Polarized: N; CompType: Capacitor; Value: 22uF; U/M: EA; Cap_F: 0.000022; Tolerance_%: 10; Value2: 10V; TaMin_C: -55; TaMax_C: 85; Cap_Case: 1206; SizeArea_mm2: 5.12; SizeAreaWB_mm2: 10.92; SizeX_mm: 3.2; SizeY_mm: 1.6; SizeZ_mm: 1.8; AEC Category: Q200; Green_Lifecycle: Active; Green_REACh: Passed
signal-integrity model Cap
simulation model Cap
footprint 1206_180
footprint 1206_180M
footprint 1206_180L
pins: 1, 2

## GRM31CR61A226ME19L
designator C?  ValueDisplayed: 22µF  (hidden comment: GRM31CR61A226ME19L)
CAP, CERM, 22 µF, 10 V,+/- 20%, X5R, 1206; Manufacturer: MuRata; Polarized: N; CompType: Capacitor; Value: 22uF; U/M: EA; Cap_F: 0.000022; Tolerance_%: 20; ESR_ohm: 0.007; Value1: 0.007 ohm; VDC_V: 10; Value2: 10V; TaMin_C: -55; TaMax_C: 85; Cap_Case: 1206; SizeArea_mm2: 5.12; SizeAreaWB_mm2: 10.92; SizeX_mm: 3.2; SizeY_mm: 1.6; SizeZ_mm: 1.8; AEC Category: Q200; Green_Lifecycle: Active; Green_REACh: Passed
signal-integrity model Cap
simulation model Cap
footprint 1206_180
footprint 1206_180M
footprint 1206_180L
pins: 1, 2

## GRM31CR61A475KA01L
designator C?  ValueDisplayed: 4.7µF  (hidden comment: GRM31CR61A475KA01L)
CAP, CERM, 4.7 µF, 10 V,+/- 10%, X5R, 1206; Manufacturer: MuRata; Polarized: N; CompType: Capacitor; Value: 4.7uF; U/M: EA; Cap_F: 0.0000047; Tolerance_%: 10; Value2: 10V; TaMin_C: -55; TaMax_C: 85; Cap_Case: 1206; SizeArea_mm2: 5.12; SizeAreaWB_mm2: 10.92; SizeX_mm: 3.2; SizeY_mm: 1.6; SizeZ_mm: 1.8; AEC Category: Q200
signal-integrity model Cap
simulation model Cap
footprint 1206_180
footprint 1206_180M
footprint 1206_180L
pins: 1, 2

## GRM31CR61A476KE15L
designator C?  ValueDisplayed: 47µF  (hidden comment: GRM31CR61A476KE15L)
CAP, CERM, 47 µF, 10 V,+/- 10%, X5R, 1206; Manufacturer: MuRata; Polarized: N; CompType: Capacitor; Value: 47uF; U/M: EA; Cap_F: 0.000047; Tolerance_%: 10; Value2: 10V; TaMin_C: -55; TaMax_C: 85; Cap_Case: 1206; SizeArea_mm2: 5.12; SizeAreaWB_mm2: 10.92; SizeX_mm: 3.2; SizeY_mm: 1.6; SizeZ_mm: 1.8; AEC Category: Q200; Green_Lifecycle: Active; Green_REACh: Passed
signal-integrity model Cap
simulation model Cap
footprint 1206_180
footprint 1206_180M
footprint 1206_180L
pins: 1, 2

## GRM31CR61C106KA88L
designator C?  ValueDisplayed: 10µF  (hidden comment: GRM31CR61C106KA88L)
CAP, CERM, 10 µF, 16 V,+/- 10%, X5R, 1206; Manufacturer: MuRata; Polarized: N; CompType: Capacitor; Value: 10uF; U/M: EA; Cap_F: 0.00001; Tolerance_%: 10; VDC_V: 16; Value2: 16V; TaMin_C: -55; TaMax_C: 85; Cap_Case: 1206; SizeArea_mm2: 5.12; SizeAreaWB_mm2: 10.92; SizeX_mm: 3.2; SizeY_mm: 1.6; SizeZ_mm: 1.8; AEC Category: Q200
signal-integrity model Cap
simulation model Cap
footprint 1206_180
footprint 1206_180M
footprint 1206_180L
pins: 1, 2

## GRM31CR61C226KE15L
designator C?  ValueDisplayed: 22µF  (hidden comment: GRM31CR61C226KE15L)
CAP, CERM, 22 µF, 16 V,+/- 10%, X5R, 1206; Manufacturer: MuRata; Polarized: N; CompType: Capacitor; Value: 22uF; U/M: EA; Cap_F: 0.000022; Tolerance_%: 10; VDC_V: 16; Value2: 16V; TaMin_C: -55; TaMax_C: 85; Cap_Case: 1206; SizeArea_mm2: 5.12; SizeAreaWB_mm2: 10.92; SizeX_mm: 3.2; SizeY_mm: 1.6; SizeZ_mm: 1.8; AEC Category: Q200; Green_Lifecycle: Active; Green_REACh: Passed
signal-integrity model Cap
simulation model Cap
footprint 1206_180
footprint 1206_180M
footprint 1206_180L
pins: 1, 2

## GRM31CR61C226ME15L
designator C?  ValueDisplayed: 22µF  (hidden comment: GRM31CR61C226ME15L)
CAP, CERM, 22 µF, 16 V,+/- 20%, X5R, 1206; Manufacturer: MuRata; Polarized: N; CompType: Capacitor; Value: 22uF; U/M: EA; Cap_F: 0.000022; Tolerance_%: 20; ESR_ohm: 0.006; Value1: 0.006 ohm; VDC_V: 16; Value2: 16V; TaMin_C: -55; TaMax_C: 85; Cap_Case: 1206; SizeArea_mm2: 5.12; SizeAreaWB_mm2: 10.92; SizeX_mm: 3.2; SizeY_mm: 1.6; SizeZ_mm: 1.8; AEC Category: Q200; Green_Lifecycle: Active; Green_REACh: Passed
signal-integrity model Cap
simulation model Cap
footprint 1206_180
footprint 1206_180M
footprint 1206_180L
pins: 1, 2

## GRM31CR61C475KA01L
designator C?  ValueDisplayed: 4.7µF  (hidden comment: GRM31CR61C475KA01L)
CAP, CERM, 4.7 µF, 16 V,+/- 10%, X5R, 1206; Manufacturer: MuRata; Polarized: N; CompType: Capacitor; Value: 4.7uF; U/M: EA; Cap_F: 0.0000047; Tolerance_%: 10; VDC_V: 16; Value2: 16V; TaMin_C: -55; TaMax_C: 85; Cap_Case: 1206; SizeArea_mm2: 5.12; SizeAreaWB_mm2: 10.92; SizeX_mm: 3.2; SizeY_mm: 1.6; SizeZ_mm: 1.8; AEC Category: Q200
signal-integrity model Cap
simulation model Cap
footprint 1206_180
footprint 1206_180M
footprint 1206_180L
pins: 1, 2

## GRM31CR61C475MA01L
designator C?  ValueDisplayed: 4.7µF  (hidden comment: GRM31CR61C475MA01L)
CAP, CERM, 4.7 µF, 16 V,+/- 20%, X5R, 1206; Manufacturer: MuRata; Polarized: N; CompType: Capacitor; Value: 4.7uF; U/M: EA; Cap_F: 0.0000047; Tolerance_%: 20; VDC_V: 16; Value2: 16V; TaMin_C: -55; TaMax_C: 85; Cap_Case: 1206; SizeArea_mm2: 5.12; SizeAreaWB_mm2: 10.92; SizeX_mm: 3.2; SizeY_mm: 1.6; SizeZ_mm: 1.8; AEC Category: Q200
signal-integrity model Cap
simulation model Cap
footprint 1206_180
footprint 1206_180M
footprint 1206_180L
pins: 1, 2

## GRM31CR61E106KA12L
designator C?  ValueDisplayed: 10µF  (hidden comment: GRM31CR61E106KA12L)
CAP, CERM, 10 µF, 25 V,+/- 10%, X5R, 1206; Manufacturer: MuRata; Polarized: N; CompType: Capacitor; Value: 10uF; U/M: EA; Cap_F: 0.00001; Tolerance_%: 10; ESR_ohm: 0.004; Value1: 0.004 ohm; VDC_V: 25; Value2: 25V; TaMin_C: -55; TaMax_C: 85; Cap_Case: 1206; SizeArea_mm2: 5.12; SizeAreaWB_mm2: 10.92; SizeX_mm: 3.2; SizeY_mm: 1.6; SizeZ_mm: 1.8; AEC Category: Q200; Green_Lifecycle: Active; Green_REACh: Passed
signal-integrity model Cap
simulation model Cap
footprint 1206_180
footprint 1206_180M
footprint 1206_180L
pins: 1, 2

## GRM31CR61E226KE15L
designator C?  ValueDisplayed: 22µF  (hidden comment: GRM31CR61E226KE15L)
CAP, CERM, 22 µF, 25 V,+/- 10%, X5R, 1206; Manufacturer: MuRata; Polarized: N; CompType: Capacitor; Value: 22uF; U/M: EA; Cap_F: 0.000022; Tolerance_%: 10; VDC_V: 25; Value2: 25V; TaMin_C: -55; TaMax_C: 85; Cap_Case: 1206; SizeArea_mm2: 5.12; SizeAreaWB_mm2: 10.92; SizeX_mm: 3.2; SizeY_mm: 1.6; SizeZ_mm: 1.8; AEC Category: Q200; Green_Lifecycle: Active; Green_REACh: Passed
signal-integrity model Cap
simulation model Cap
footprint 1206_180
footprint 1206_180M
footprint 1206_180L
pins: 1, 2

## GRM31CR61E335KA88L
designator C?  ValueDisplayed: 3.3µF  (hidden comment: GRM31CR61E335KA88L)
CAP, CERM, 3.3 µF, 25 V,+/- 10%, X5R, 1206; Manufacturer: MuRata; Polarized: N; CompType: Capacitor; Value: 3.3uF; U/M: EA; Cap_F: 0.0000033; Tolerance_%: 10; VDC_V: 25; Value2: 25V; TaMin_C: -55; TaMax_C: 85; Cap_Case: 1206; SizeArea_mm2: 5.12; SizeAreaWB_mm2: 10.92; SizeX_mm: 3.2; SizeY_mm: 1.6; SizeZ_mm: 1.8; AEC Category: Q200
signal-integrity model Cap
simulation model Cap
footprint 1206_180
footprint 1206_180M
footprint 1206_180L
pins: 1, 2

## GRM31CR61E475KA88L
designator C?  ValueDisplayed: 4.7µF  (hidden comment: GRM31CR61E475KA88L)
CAP, CERM, 4.7 µF, 25 V,+/- 10%, X5R, 1206; Manufacturer: MuRata; Polarized: N; CompType: Capacitor; Value: 4.7uF; U/M: EA; Cap_F: 0.0000047; Tolerance_%: 10; VDC_V: 25; Value2: 25V; TaMin_C: -55; TaMax_C: 85; Cap_Case: 1206; SizeArea_mm2: 5.12; SizeAreaWB_mm2: 10.92; SizeX_mm: 3.2; SizeY_mm: 1.6; SizeZ_mm: 1.8; AEC Category: Q200
signal-integrity model Cap
simulation model Cap
footprint 1206_180
footprint 1206_180M
footprint 1206_180L
pins: 1, 2

## GRM31CR61H106KA12L
designator C?  ValueDisplayed: 10µF  (hidden comment: GRM31CR61H106KA12L)
CAP, CERM, 10 µF, 50 V,+/- 10%, X5R, 1206; Manufacturer: MuRata; Polarized: N; CompType: Capacitor; Value: 10uF; U/M: EA; Cap_F: 0.00001; Tolerance_%: 10; VDC_V: 50; Value2: 50V; TaMin_C: -55; TaMax_C: 85; Cap_Case: 1206; SizeArea_mm2: 5.12; SizeAreaWB_mm2: 10.92; SizeX_mm: 3.2; SizeY_mm: 1.6; SizeZ_mm: 1.8; AEC Category: Q200; Green_Lifecycle: Active; Green_REACh: Passed
signal-integrity model Cap
simulation model Cap
footprint 1206_180
footprint 1206_180M
footprint 1206_180L
pins: 1, 2

## GRM31CR61H225KA88L
designator C?  ValueDisplayed: 2.2µF  (hidden comment: GRM31CR61H225KA88L)
CAP, CERM, 2.2 µF, 50 V,+/- 10%, X5R, 1206; Manufacturer: MuRata; Polarized: N; CompType: Capacitor; Value: 2.2uF; U/M: EA; Cap_F: 0.0000022; Tolerance_%: 10; VDC_V: 50; Value2: 50V; TaMin_C: -55; TaMax_C: 85; Cap_Case: 1206; SizeArea_mm2: 5.12; SizeAreaWB_mm2: 10.92; SizeX_mm: 3.2; SizeY_mm: 1.6; SizeZ_mm: 1.8; AEC Category: Q200; Green_Lifecycle: Active; Green_REACh: Passed
signal-integrity model Cap
simulation model Cap
footprint 1206_180
footprint 1206_180M
footprint 1206_180L
pins: 1, 2

## GRM31CR70J106KA01L
designator C?  ValueDisplayed: 10µF  (hidden comment: GRM31CR70J106KA01L)
CAP, CERM, 10 µF, 6.3 V,+/- 10%, X7R, 1206; Manufacturer: MuRata; Polarized: N; CompType: Capacitor; Value: 10uF; U/M: EA; Cap_F: 0.00001; Tolerance_%: 10; VDC_V: 6.3; Value2: 6.3V; TaMin_C: -55; TaMax_C: 125; Cap_Case: 1206; SizeArea_mm2: 5.12; SizeAreaWB_mm2: 10.92; SizeX_mm: 3.2; SizeY_mm: 1.6; SizeZ_mm: 1.8; AEC Category: Q200
signal-integrity model Cap
simulation model Cap
footprint 1206_180
footprint 1206_180M
footprint 1206_180L
pins: 1, 2

## GRM31CR70J226KE19L
designator C?  ValueDisplayed: 22µF  (hidden comment: GRM31CR70J226KE19L)
CAP, CERM, 22 µF, 6.3 V,+/- 10%, X7R, 1206; Manufacturer: MuRata; Polarized: N; CompType: Capacitor; Value: 22uF; U/M: EA; Cap_F: 0.000022; Tolerance_%: 10; VDC_V: 6.3; Value2: 6.3V; TaMin_C: -55; TaMax_C: 125; Cap_Case: 1206; SizeArea_mm2: 5.12; SizeAreaWB_mm2: 10.92; SizeX_mm: 3.2; SizeY_mm: 1.6; SizeZ_mm: 1.8; AEC Category: Q200
signal-integrity model Cap
simulation model Cap
footprint 1206_180
footprint 1206_180M
footprint 1206_180L
pins: 1, 2

## GRM31CR71A106KA01L
designator C?  ValueDisplayed: 10µF  (hidden comment: GRM31CR71A106KA01L)
CAP, CERM, 10 µF, 10 V,+/- 10%, X7R, 1206; Manufacturer: MuRata; Polarized: N; CompType: Capacitor; Value: 10uF; U/M: EA; Cap_F: 0.00001; Tolerance_%: 10; Value2: 10V; TaMin_C: -55; TaMax_C: 125; Cap_Case: 1206; SizeArea_mm2: 5.12; SizeAreaWB_mm2: 10.92; SizeX_mm: 3.2; SizeY_mm: 1.6; SizeZ_mm: 1.8; AEC Category: Q200; Green_Lifecycle: Active; Green_REACh: Passed
signal-integrity model Cap
simulation model Cap
footprint 1206_180
footprint 1206_180M
footprint 1206_180L
pins: 1, 2

## GRM31CR71A226KE15L
designator C?  ValueDisplayed: 22µF  (hidden comment: GRM31CR71A226KE15L)
CAP, CERM, 22 µF, 10 V,+/- 10%, X7R, 1206; Manufacturer: MuRata; Polarized: N; CompType: Capacitor; Value: 22uF; U/M: EA; Cap_F: 0.000022; Tolerance_%: 10; Value2: 10V; TaMin_C: -55; TaMax_C: 125; Cap_Case: 1206; SizeArea_mm2: 5.12; SizeAreaWB_mm2: 10.92; SizeX_mm: 3.2; SizeY_mm: 1.6; SizeZ_mm: 1.8; AEC Category: Q200; Green_Lifecycle: Active; Green_REACh: Passed
signal-integrity model Cap
simulation model Cap
footprint 1206_180
footprint 1206_180M
footprint 1206_180L
pins: 1, 2

## GRM31CR71A226ME15L
designator C?  ValueDisplayed: 22µF  (hidden comment: GRM31CR71A226ME15L)
CAP, CERM, 22 µF, 10 V,+/- 20%, X7R, 1206; Manufacturer: MuRata; Polarized: N; CompType: Capacitor; Value: 22uF; U/M: EA; Cap_F: 0.000022; Tolerance_%: 20; VDC_V: 10; Value2: 10V; TaMin_C: -55; TaMax_C: 125; Cap_Case: 1206; SizeArea_mm2: 5.12; SizeAreaWB_mm2: 10.92; SizeX_mm: 3.2; SizeY_mm: 1.6; SizeZ_mm: 1.8; AEC Category: Q200; Green_Lifecycle: Active; Green_REACh: Passed
signal-integrity model Cap
simulation model Cap
footprint 1206_180
footprint 1206_180M
footprint 1206_180L
pins: 1, 2

## GRM31CR71A475KA01L
designator C?  ValueDisplayed: 4.7µF  (hidden comment: GRM31CR71A475KA01L)
CAP, CERM, 4.7 µF, 10 V,+/- 10%, X7R, 1206; Manufacturer: MuRata; Polarized: N; CompType: Capacitor; Value: 4.7uF; U/M: EA; Cap_F: 0.0000047; Tolerance_%: 10; Value2: 10V; TaMin_C: -55; TaMax_C: 125; Cap_Case: 1206; SizeArea_mm2: 5.12; SizeAreaWB_mm2: 10.92; SizeX_mm: 3.2; SizeY_mm: 1.6; SizeZ_mm: 1.8; AEC Category: Q200
signal-integrity model Cap
simulation model Cap
footprint 1206_180
footprint 1206_180M
footprint 1206_180L
pins: 1, 2

## GRM31CR71C106KAC7L
designator C?  ValueDisplayed: 10µF  (hidden comment: GRM31CR71C106KAC7L)
CAP, CERM, 10 µF, 16 V,+/- 10%, X7R, 1206; Manufacturer: MuRata; Polarized: N; CompType: Capacitor; Value: 10uF; U/M: EA; Cap_F: 0.00001; Tolerance_%: 10; VDC_V: 16; Value2: 16V; TaMin_C: -55; TaMax_C: 125; Cap_Case: 1206; SizeArea_mm2: 5.12; SizeAreaWB_mm2: 10.92; SizeX_mm: 3.2; SizeY_mm: 1.6; SizeZ_mm: 1.8; AEC Category: Q200; Green_Lifecycle: Active; Green_REACh: Passed
signal-integrity model Cap
simulation model Cap
footprint 1206_180
footprint 1206_180M
footprint 1206_180L
pins: 1, 2

## GRM31CR71C335KA01L
designator C?  ValueDisplayed: 3.3µF  (hidden comment: GRM31CR71C335KA01L)
CAP, CERM, 3.3 µF, 16 V,+/- 10%, X7R, 1206; Manufacturer: MuRata; Polarized: N; CompType: Capacitor; Value: 3.3uF; U/M: EA; Cap_F: 0.0000033; Tolerance_%: 10; VDC_V: 16; Value2: 16V; TaMin_C: -55; TaMax_C: 125; Cap_Case: 1206; SizeArea_mm2: 5.12; SizeAreaWB_mm2: 10.92; SizeX_mm: 3.2; SizeY_mm: 1.6; SizeZ_mm: 1.8; AEC Category: Q200
signal-integrity model Cap
simulation model Cap
footprint 1206_180
footprint 1206_180M
footprint 1206_180L
pins: 1, 2

## GRM31CR71C475KA01L
designator C?  ValueDisplayed: 4.7µF  (hidden comment: GRM31CR71C475KA01L)
CAP, CERM, 4.7 µF, 16 V,+/- 10%, X7R, 1206; Manufacturer: MuRata; Polarized: N; CompType: Capacitor; Value: 4.7uF; U/M: EA; Cap_F: 0.0000047; Tolerance_%: 10; VDC_V: 16; Value2: 16V; TaMin_C: -55; TaMax_C: 125; Cap_Case: 1206; SizeArea_mm2: 5.12; SizeAreaWB_mm2: 10.92; SizeX_mm: 3.2; SizeY_mm: 1.6; SizeZ_mm: 1.8; AEC Category: Q200
signal-integrity model Cap
simulation model Cap
footprint 1206_180
footprint 1206_180M
footprint 1206_180L
pins: 1, 2

## GRM31CR71E106KA12L
designator C?  ValueDisplayed: 10µF  (hidden comment: GRM31CR71E106KA12L)
CAP, CERM, 10 µF, 25 V,+/- 10%, X7R, 1206; Manufacturer: MuRata; Polarized: N; CompType: Capacitor; Value: 10uF; U/M: EA; Cap_F: 0.00001; Tolerance_%: 10; VDC_V: 25; Value2: 25V; TaMin_C: -55; TaMax_C: 125; Cap_Case: 1206; SizeArea_mm2: 5.12; SizeAreaWB_mm2: 10.92; SizeX_mm: 3.2; SizeY_mm: 1.6; SizeZ_mm: 1.8; AEC Category: Q200; Green_Lifecycle: Active; Green_REACh: Passed
signal-integrity model Cap
simulation model Cap
footprint 1206_180
footprint 1206_180M
footprint 1206_180L
pins: 1, 2

## GRM31CR71E335KA88L
designator C?  ValueDisplayed: 3.3µF  (hidden comment: GRM31CR71E335KA88L)
CAP, CERM, 3.3 µF, 25 V,+/- 10%, X7R, 1206; Manufacturer: MuRata; Polarized: N; CompType: Capacitor; Value: 3.3uF; U/M: EA; Cap_F: 0.0000033; Tolerance_%: 10; VDC_V: 25; Value2: 25V; TaMin_C: -55; TaMax_C: 125; Cap_Case: 1206; SizeArea_mm2: 5.12; SizeAreaWB_mm2: 10.92; SizeX_mm: 3.2; SizeY_mm: 1.6; SizeZ_mm: 1.8; AEC Category: Q200
signal-integrity model Cap
simulation model Cap
footprint 1206_180
footprint 1206_180M
footprint 1206_180L
pins: 1, 2

## GRM31CR71E475KA88L
designator C?  ValueDisplayed: 4.7µF  (hidden comment: GRM31CR71E475KA88L)
CAP, CERM, 4.7 µF, 25 V,+/- 10%, X7R, 1206; Manufacturer: MuRata; Polarized: N; CompType: Capacitor; Value: 4.7uF; U/M: EA; Cap_F: 0.0000047; Tolerance_%: 10; VDC_V: 25; Value2: 25V; TaMin_C: -55; TaMax_C: 125; Cap_Case: 1206; SizeArea_mm2: 5.12; SizeAreaWB_mm2: 10.92; SizeX_mm: 3.2; SizeY_mm: 1.6; SizeZ_mm: 1.8; AEC Category: Q200; Green_Lifecycle: Active; Green_REACh: Passed
signal-integrity model Cap
simulation model Cap
footprint 1206_180
footprint 1206_180M
footprint 1206_180L
pins: 1, 2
